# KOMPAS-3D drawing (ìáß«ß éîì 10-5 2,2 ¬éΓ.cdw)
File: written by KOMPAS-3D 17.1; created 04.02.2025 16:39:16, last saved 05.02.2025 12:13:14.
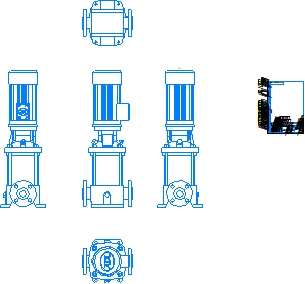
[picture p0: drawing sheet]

Sheet 1: A4, portrait

Title block, sheet 1: name: Насос ВМН 10-5 2,2 / кВт; designation: Насос ВМН 10-5 2,2 кВт; material: Сталь 10  ГОСТ 1050-2013; mass: 134,74; sheets: 1; sheet format: A4; stored path: \\adlc.lan\data\АДЛ_ПКД\3D-модели\ADL production\Насосы ГРАНПАМП\Насосы ВМН\ВМН10\KOMPAS 3D\Насос ВМН 10-5 2,2 кВт.cdw

Views: Вид 1, Спереди, Проекционный вид 2, Проекционный вид 3, Проекционный вид 4, Проекционный вид 5
Referenced files in \\adlc.lan\data\АДЛ_ПКД\3D-модели\ADL production\Насосы ГРАНПАМП\Насосы ВМН\ВМН10\KOMPAS 3D\: ВМН 10-5 2,2 кВт.m3d, Насос ВМН 10-5 2,2 кВт.m3d
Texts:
  Andrey
  АДЛ
Dimensions and other numbers on the sheet: 1:1; 1; 134,74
